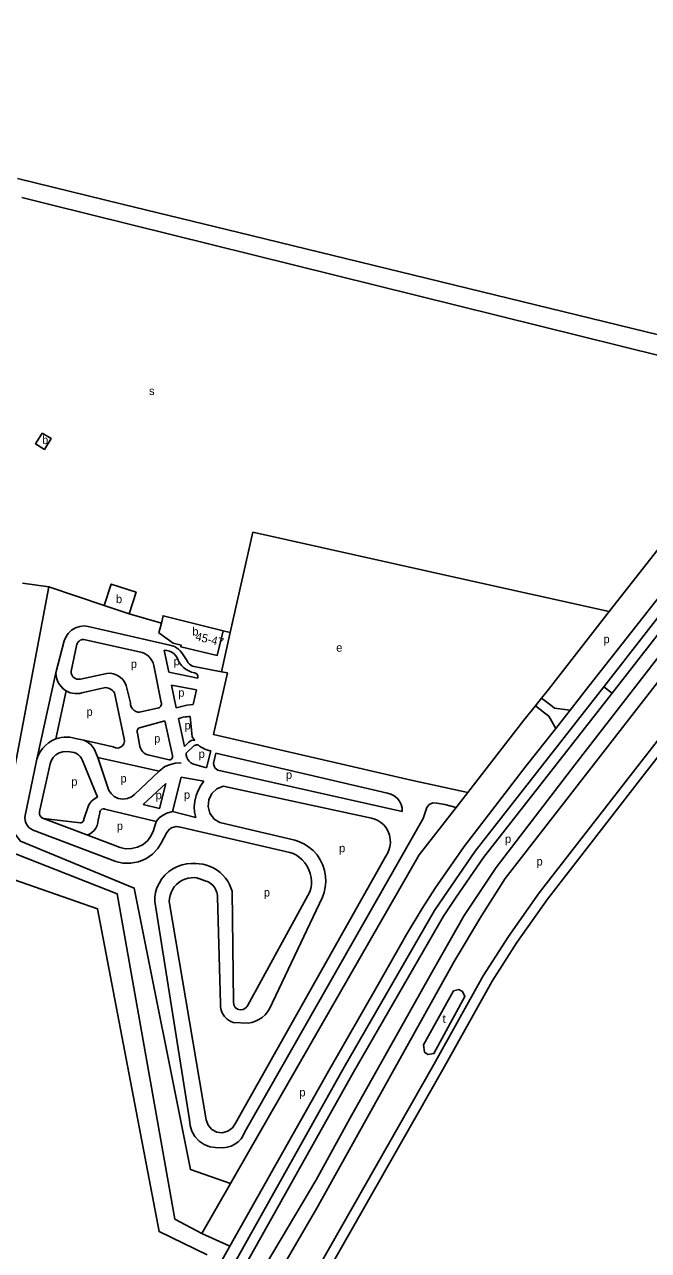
# Model space of a CAD drawing. Extents: x 153608 to 155459, y 385052 to 386919.
# Drawn here: x 154062 to 154363, y 385663 to 386253 of the extents above; entities that cross this region are included whole.
import ezdxf

# ---------------------------------------------------------------- set-up
doc = ezdxf.new("R2010")
doc.units = 0
for name, color, linetype in [('BLT_Basislijn', 7, 'Continuous'), ('BLT_Bebouwing', 7, 'Continuous'), ('BLT_Centroide', 7, 'Continuous'), ('BLT_Gemeentegrens', 7, 'Continuous'), ('BLT_Huisnummer_reeks', 7, 'Continuous'), ('BLT_Vlakafsluiter', 7, 'Continuous')]:
    doc.layers.add(name, color=color, linetype=linetype)

msp = doc.modelspace()

# ---------------------------------------------------------------- linework, layer by layer
at = {"layer": 'BLT_Basislijn'}
for p, q in [((154343.74, 385970.46), (154428.43, 386078.64)), ((154380, 385993.06), (154333.96, 385934.36)), ((154112.53, 385969.36), (154128.11, 385964.85)), ((154314.48, 385932.86), (154343.74, 385970.46)), ((154132.15, 385954.21), (154092.92, 385963.26)), ((154081.38, 385956.23), (154077.28, 385940.91)), ((154090.78, 385957), (154118.86, 385950.68)), ((154161.31, 385960.37), (154157.84, 385961.14)), ((154084.67, 385941.66), (154087.47, 385954.68)), ((154129.5, 385951.72), (154131.67, 385941.23)), ((154124.43, 385944.44), (154127.98, 385926.63)), ((154138.63, 385949.56), (154140.28, 385947.07)), ((154068.09, 385899.23), (154077.28, 385940.91)), ((154101.77, 385940.59), (154089.17, 385937.87)), ((154131.67, 385941.23), (154145.65, 385938.27)), ((154157.02, 385941.36), (154144.65, 385943.72)), ((154159.98, 385940.8), (154157.02, 385941.36)), ((154101.16, 385933.72), (154089.86, 385931.2)), ((154113.19, 385926.34), (154111.16, 385934.8)), ((154132.98, 385934.91), (154135.26, 385923.92)), ((154132.98, 385934.91), (154144.99, 385932.74)), ((154144.99, 385932.74), (154143.36, 385925.62)), ((154311.21, 385928.66), (154314.48, 385932.86)), ((154082.19, 385932.19), (154077.25, 385908.99)), ((154105.51, 385931.23), (154110.23, 385909.11)), ((154308.22, 385924.92), (154311.21, 385928.66)), ((154126.84, 385924.04), (154117.64, 385921.89)), ((154302.67, 385918), (154308.22, 385924.92)), ((154129.85, 385917.79), (154117.5, 385914.35)), ((154129.85, 385917.79), (154133.45, 385900.97)), ((154136.31, 385918.84), (154139.19, 385905.37)), ((154275.66, 385883.18), (154302.67, 385918)), ((154090.78, 385908.37), (154086.74, 385909.29)), ((154116.64, 385911.76), (154117.62, 385906.31)), ((154104.84, 385905.16), (154090.78, 385908.37)), ((154143.96, 385905.81), (154140.03, 385902.16)), ((154151.93, 385903.35), (154149.84, 385895.11)), ((154068.09, 385899.23), (154062.52, 385872.18)), ((154090.12, 385898.63), (154097.43, 385880.95)), ((154097.51, 385900.12), (154102.83, 385884.24)), ((154131.9, 385899.01), (154121.54, 385901.4)), ((154154.36, 385902.2), (154153.55, 385898.62)), ((154154.36, 385902.2), (154237.02, 385882.83)), ((154069.55, 385874.64), (154074.49, 385896.95)), ((154144.14, 385896.64), (154149.84, 385895.11)), ((154244.1, 385874), (154155.25, 385893.99)), ((154137.58, 385890.66), (154133.49, 385874.04)), ((154137.58, 385890.66), (154148.62, 385888.63)), ((154229.35, 385870.87), (154157.87, 385886.23)), ((154248.4, 385889.17), (154275.66, 385883.18)), ((154275.66, 385883.18), (154270.01, 385875.97)), ((154093.02, 385876.99), (154090.81, 385870.4)), ((154133.49, 385874.04), (154144.62, 385871.16)), ((154252.22, 385853.21), (154270.01, 385875.97)), ((154071.38, 385870.62), (154088.94, 385868.53)), ((154071.38, 385870.62), (154092.22, 385862.74)), ((154098.47, 385873.48), (154097.71, 385869.89)), ((154192.41, 385860.2), (154156.31, 385868.68)), ((154168.29, 385719.69), (154254.17, 385870.67)), ((154106.12, 385850.02), (154066.38, 385865.11)), ((154108.29, 385856.66), (154092.22, 385862.74)), ((154130.73, 385863.86), (154128.24, 385859.14)), ((154189.99, 385854.36), (154137.28, 385866.51)), ((154236.21, 385852.58), (154163.78, 385723.83)), ((154155.15, 385832.84), (154156.52, 385781.55)), ((154162.17, 385835.65), (154162.79, 385782.29)), ((154199.64, 385835.32), (154169.57, 385780.49)), ((154205.67, 385832.83), (154180.22, 385779.05)), ((154124.9, 385830.74), (154141.68, 385725.43)), ((154131.9, 385830.75), (154149.74, 385725.43)), ((154162.65, 385772.46), (154169.84, 385772.04)), ((154263.62, 385749.77), (154197.88, 385634.26)), ((154154.12, 385712.15), (154158, 385712.09)), ((154147.56, 385670.72), (154161.11, 385664.72)), ((154161.11, 385664.72), (154156.56, 385656.65))]:
    msp.add_line(p, q, dxfattribs=at)
for points in [[(154745.51, 386395.94), (154651.35, 386298.5), (154593.06, 386237.32), (154585.71, 386228.52), (154550.39, 386183.09), (154493.67, 386110.22), (154463.08, 386071.36), (154405.83, 385998.1), (154327.19, 385896.61), (154289.38, 385847.11), (154273.88, 385824), (154259.18, 385798.01), (154218.87, 385726.19), (154202.46, 385696.25), (154159, 385622.99), (154144.16, 385603.56), (154139.31, 385598.7), (154138.16, 385595.98)], [(154754.37, 386395.71), (154615.6, 386250.29), (154597.76, 386230.66), (154569.71, 386196.31), (154538.03, 386154.95), (154452.53, 386046.43), (154357.94, 385924.71), (154293.71, 385841.85), (154282.27, 385823.81), (154269.07, 385801.81), (154202.93, 385683.02), (154166.56, 385620.26), (154155.85, 385605), (154148.23, 385596.21), (154143.53, 385591.51), (154141.05, 385591.43)], [(154640.74, 386253.44), (154625.05, 386236.37), (154609.33, 386219.18), (154597.17, 386204.41), (154577.98, 386180.02), (154525.27, 386111.88), (154477.44, 386050.65), (154421.65, 385978.46), (154354.9, 385892.7), (154310.03, 385834.83), (154295.19, 385813.79), (154283.1, 385794.92), (154259.28, 385752.24)], [(154341.17, 385934.15), (154392.73, 386000.27), (154500.64, 386139.76), (154565.87, 386224.01), (154579.08, 386240.21), (154593.88, 386257.02)], [(154597.57, 386253.65), (154582.89, 386236.98), (154569.79, 386220.89), (154504.59, 386136.7), (154396.67, 385997.21), (154345.11, 385931.07)], [(154060.93, 386169.83), (154073.68, 386166.67), (154428.43, 386078.64)], [(154161.31, 385960.37), (154172.2, 386008.69)], [(154172.2, 386008.69), (154272.86, 385986.18)], [(154272.86, 385986.18), (154343.74, 385970.46)], [(154073.89, 385982.25), (154053.98, 385876.82), (154054.7, 385867.21), (154060.23, 385859.76), (154115.02, 385837.17), (154142.08, 385701.54), (154161.36, 385694.78)], [(154061.3, 385983.98), (154073.89, 385982.25)], [(154073.89, 385982.25), (154100.55, 385973.24)], [(154092.92, 385963.26), (154090.93, 385963.45), (154088.83, 385963.21), (154086.76, 385962.5), (154084.87, 385961.35), (154083.3, 385959.84), (154082.13, 385958.08), (154081.38, 385956.23)], [(154090.78, 385957), (154090.19, 385956.95), (154089.6, 385956.8), (154089.02, 385956.53), (154088.51, 385956.17), (154088.07, 385955.72), (154087.72, 385955.21), (154087.47, 385954.68)], [(154157.02, 385941.36), (154161.31, 385960.37)], [(154118.86, 385950.68), (154119.99, 385950.21), (154121.06, 385949.57), (154122.04, 385948.76), (154122.89, 385947.81), (154123.58, 385946.74), (154124.09, 385945.61), (154124.43, 385944.44)], [(154129.5, 385951.72), (154130.71, 385951.66), (154131.94, 385951.36), (154133.12, 385950.83), (154134.19, 385950.07), (154135.08, 385949.13), (154135.77, 385948.07), (154136.23, 385946.95)], [(154138.63, 385949.56), (154137.99, 385950.52), (154137.23, 385951.41), (154136.36, 385952.21), (154135.39, 385952.91), (154134.35, 385953.48), (154133.27, 385953.91), (154132.15, 385954.21)], [(154136.23, 385946.95), (154136.89, 385945.68), (154137.74, 385944.47), (154138.78, 385943.39), (154139.97, 385942.47), (154141.28, 385941.75), (154142.66, 385941.24), (154144.07, 385940.94)], [(154144.65, 385943.72), (154143.86, 385943.85), (154143.07, 385944.11), (154142.32, 385944.51), (154141.64, 385945.03), (154141.07, 385945.65), (154140.61, 385946.34), (154140.28, 385947.07)], [(154082.19, 385932.19), (154081.01, 385933.04), (154079.94, 385934.08), (154079.02, 385935.27), (154078.27, 385936.6), (154077.73, 385938.01), (154077.4, 385939.47), (154077.28, 385940.91)], [(154084.67, 385941.66), (154084.7, 385940.77), (154084.98, 385939.83), (154085.55, 385938.96), (154086.36, 385938.28), (154087.32, 385937.87), (154088.29, 385937.75), (154089.17, 385937.87)], [(154101.77, 385940.59), (154103.39, 385940.64), (154105.07, 385940.37), (154106.71, 385939.76), (154108.21, 385938.84), (154109.48, 385937.65), (154110.48, 385936.27), (154111.16, 385934.8)], [(154144.07, 385940.94), (154144.5, 385940.78), (154144.92, 385940.52), (154145.27, 385940.15), (154145.54, 385939.71), (154145.69, 385939.22), (154145.72, 385938.73), (154145.65, 385938.27)], [(154248.4, 385889.17), (154153.23, 385911.1), (154159.98, 385940.8)], [(154101.16, 385933.72), (154101.89, 385933.67), (154102.62, 385933.5), (154103.33, 385933.23), (154103.99, 385932.85), (154104.59, 385932.37), (154105.1, 385931.83), (154105.51, 385931.23)], [(154133.5, 385604.62), (154133.38, 385605.56), (154133.36, 385606.42), (154133.41, 385607.28), (154133.55, 385608.13), (154133.76, 385608.97), (154134.05, 385609.78), (154134.42, 385610.56), (154134.86, 385611.3), (154135.36, 385612.01), (154138.54, 385616.04), (154142.15, 385620.5), (154164.86, 385659.31), (154216.2, 385750.91), (154259.7, 385826.29), (154265.85, 385835.59), (154279.22, 385854.9), (154341.17, 385934.15)], [(154333.96, 385934.36), (154324.93, 385922.88)], [(154089.86, 385931.2), (154088.77, 385930.96), (154087.64, 385930.84), (154086.5, 385930.86), (154085.36, 385931), (154084.25, 385931.28), (154083.18, 385931.68), (154082.19, 385932.19)], [(154345.11, 385931.07), (154283.24, 385851.94), (154269.99, 385832.79), (154263.95, 385823.66), (154220.55, 385748.44), (154169.2, 385656.83), (154146.27, 385617.65), (154142.45, 385612.92), (154142.19, 385612.59)], [(154315.61, 385925.27), (154311.21, 385928.66)], [(154117.64, 385921.89), (154116.72, 385921.98), (154115.77, 385922.3), (154114.89, 385922.84), (154114.15, 385923.58), (154113.6, 385924.47), (154113.29, 385925.41), (154113.19, 385926.34)], [(154127.98, 385926.63), (154128.09, 385926.22), (154128.11, 385925.77), (154128.03, 385925.32), (154127.84, 385924.88), (154127.55, 385924.52), (154127.21, 385924.23), (154126.84, 385924.04)], [(154143.36, 385925.62), (154140.39, 385925.34), (154135.26, 385923.92)], [(154312.69, 385921.51), (154308.22, 385924.92)], [(154318.01, 385914.09), (154314.61, 385920.05), (154312.69, 385921.51)], [(154324.93, 385922.88), (154317.48, 385923.82), (154315.61, 385925.27)], [(154324.93, 385922.88), (154318.01, 385914.09)], [(154141.94, 385919.81), (154141.13, 385919.79), (154140.31, 385919.73), (154139.49, 385919.63), (154138.68, 385919.49), (154137.88, 385919.31), (154137.09, 385919.09), (154136.31, 385918.84)], [(154141.94, 385919.81), (154142.62, 385913.2), (154142.94, 385910.04), (154144.1, 385908.41), (154142.42, 385908.27), (154141.4, 385907.46), (154139.19, 385905.37)], [(154381.51, 385918.75), (154358.84, 385889.63), (154314.05, 385831.86), (154299.34, 385811), (154287.39, 385792.35), (154263.62, 385749.77)], [(154077.25, 385908.99), (154075.48, 385908.2), (154073.79, 385907.17), (154072.24, 385905.9), (154070.86, 385904.43), (154069.69, 385902.8), (154068.77, 385901.05), (154068.09, 385899.23)], [(154086.74, 385909.29), (154085.41, 385909.6), (154084.05, 385909.8), (154082.67, 385909.88), (154081.28, 385909.83), (154079.9, 385909.67), (154078.56, 385909.39), (154077.25, 385908.99)], [(154110.23, 385909.11), (154110.34, 385907.91), (154110.02, 385906.7), (154109.33, 385905.68), (154108.38, 385904.98), (154107.19, 385904.63), (154105.94, 385904.69), (154104.84, 385905.16)], [(154117.5, 385914.35), (154117.16, 385914.13), (154116.86, 385913.82), (154116.62, 385913.44), (154116.48, 385913.01), (154116.44, 385912.57), (154116.5, 385912.14), (154116.64, 385911.76)], [(154318.01, 385914.09), (154303.83, 385896.06), (154273.91, 385857.24), (154259.91, 385837.08)], [(154097.51, 385900.12), (154095.74, 385904.28), (154094.26, 385906.2), (154092.32, 385907.66), (154090.78, 385908.37)], [(154117.62, 385906.31), (154117.73, 385905.4), (154118.02, 385904.49), (154118.48, 385903.62), (154119.1, 385902.84), (154119.85, 385902.2), (154120.67, 385901.72), (154121.54, 385901.4)], [(154145.77, 385906.21), (154145.51, 385906.2), (154145.24, 385906.17), (154144.98, 385906.13), (154144.72, 385906.08), (154144.46, 385906), (154144.21, 385905.92), (154143.96, 385905.81)], [(154151.93, 385903.35), (154150.97, 385903.52), (154150.02, 385903.78), (154149.09, 385904.12), (154148.19, 385904.54), (154147.34, 385905.03), (154146.53, 385905.59), (154145.77, 385906.21)], [(154084, 385902.8), (154082.36, 385903.01), (154080.6, 385902.85), (154078.85, 385902.28), (154077.27, 385901.31), (154075.97, 385900.01), (154075.04, 385898.51), (154074.49, 385896.95)], [(154084, 385902.8), (154085.07, 385902.71), (154086.16, 385902.43), (154087.21, 385901.96), (154088.16, 385901.31), (154088.99, 385900.51), (154089.64, 385899.6), (154090.12, 385898.63)], [(154097.51, 385900.12), (154126.97, 385893.55)], [(154126.97, 385893.55), (154129.73, 385895.66), (154132.01, 385896.59), (154134.8, 385897.27), (154137.65, 385897.55)], [(154133.45, 385900.97), (154133.53, 385900.6), (154133.51, 385900.18), (154133.35, 385899.75), (154133.07, 385899.38), (154132.69, 385899.13), (154132.28, 385899.01), (154131.9, 385899.01)], [(154140.03, 385902.16), (154140.12, 385901.15), (154140.4, 385900.14), (154140.87, 385899.17), (154141.51, 385898.3), (154142.31, 385897.57), (154143.2, 385897.01), (154144.14, 385896.64)], [(154153.55, 385898.62), (154153.33, 385897.93), (154153.26, 385897.15), (154153.36, 385896.36), (154153.64, 385895.59), (154154.08, 385894.92), (154154.63, 385894.38), (154155.25, 385893.99)], [(154126.97, 385893.55), (154115.14, 385882.27)], [(154148.62, 385888.63), (154147.07, 385886.55), (154145.78, 385884.22), (154144.81, 385881.7), (154144.2, 385879.06), (154143.97, 385876.37), (154144.12, 385873.71), (154144.62, 385871.16)], [(154157.87, 385886.23), (154154.85, 385885), (154152.34, 385882.66), (154150.88, 385879.61), (154150.6, 385876.43), (154151.5, 385873.18), (154153.55, 385870.43), (154156.31, 385868.68)], [(154097.43, 385880.95), (154096.65, 385880.61), (154095.9, 385880.18), (154095.19, 385879.67), (154094.53, 385879.08), (154093.95, 385878.43), (154093.45, 385877.73), (154093.02, 385876.99)], [(154102.83, 385884.24), (154103.86, 385882.67), (154105.4, 385881.29), (154107.38, 385880.33), (154109.6, 385879.98), (154111.78, 385880.27), (154113.67, 385881.1), (154115.14, 385882.27)], [(154237.02, 385882.83), (154238.62, 385882.38), (154240.19, 385881.57), (154241.59, 385880.42), (154242.74, 385878.99), (154243.56, 385877.37), (154244.01, 385875.67), (154244.1, 385874)], [(154069.55, 385874.64), (154069.39, 385874.01), (154069.36, 385873.31), (154069.5, 385872.6), (154069.81, 385871.93), (154070.25, 385871.35), (154070.8, 385870.91), (154071.38, 385870.62)], [(154100.96, 385875.2), (154100.52, 385875.31), (154100.01, 385875.3), (154099.5, 385875.14), (154099.05, 385874.82), (154098.71, 385874.4), (154098.52, 385873.94), (154098.47, 385873.48)], [(154100.96, 385875.2), (154125.66, 385869.24)], [(154125.66, 385869.24), (154126.97, 385870.93), (154128.71, 385872.18), (154130.81, 385873.27), (154133.49, 385874.04)], [(154254.17, 385870.67), (154255.93, 385875.97), (154257.13, 385877.44), (154258.85, 385878.24), (154260.7, 385878.15), (154264.6, 385877.35), (154270.01, 385875.97)], [(154062.52, 385872.18), (154062.4, 385871), (154062.52, 385869.76), (154062.9, 385868.53), (154063.52, 385867.4), (154064.35, 385866.42), (154065.33, 385865.65), (154066.38, 385865.11)], [(154090.81, 385870.4), (154090.77, 385870.01), (154090.64, 385869.62), (154090.41, 385869.25), (154090.1, 385868.93), (154089.73, 385868.71), (154089.33, 385868.57), (154088.94, 385868.53)], [(154097.71, 385869.89), (154097.59, 385868.57), (154097.22, 385867.24), (154096.59, 385865.97), (154095.72, 385864.84), (154094.65, 385863.9), (154093.46, 385863.19), (154092.22, 385862.74)], [(154125.66, 385869.24), (154124.3, 385864.9)], [(154229.35, 385870.87), (154230.84, 385870.42), (154232.34, 385869.73), (154233.8, 385868.78), (154235.15, 385867.57), (154236.34, 385866.11), (154237.3, 385864.45), (154237.98, 385862.64), (154238.35, 385860.76), (154238.41, 385858.89), (154238.18, 385857.08), (154237.7, 385855.41), (154237.03, 385853.9), (154236.21, 385852.58)], [(154124.3, 385864.9), (154123.22, 385862.45), (154121.54, 385860.16), (154119.29, 385858.23), (154116.62, 385856.86), (154113.74, 385856.15), (154110.9, 385856.12), (154108.29, 385856.66)], [(154137.28, 385866.51), (154136.26, 385866.73), (154135.17, 385866.75), (154134.06, 385866.55), (154133.01, 385866.12), (154132.07, 385865.5), (154131.3, 385864.73), (154130.73, 385863.86)], [(154038.94, 385861.11), (154106.86, 385834.44), (154134.59, 385677.64)], [(154128.24, 385859.14), (154126.36, 385856.16), (154123.8, 385853.46), (154120.64, 385851.28), (154117.05, 385849.8), (154113.27, 385849.12), (154109.55, 385849.22), (154106.12, 385850.02)], [(154192.41, 385860.2), (154194.68, 385859.45), (154196.96, 385858.37), (154199.16, 385856.95), (154201.22, 385855.2), (154203.07, 385853.13), (154204.64, 385850.8), (154205.87, 385848.25), (154206.73, 385845.58), (154207.21, 385842.85), (154207.3, 385840.14), (154207.05, 385837.54), (154206.49, 385835.08), (154205.67, 385832.83)], [(154161.36, 385694.78), (154170.2, 385710.19), (154252.22, 385853.21)], [(154189.99, 385854.36), (154191.56, 385853.75), (154193.1, 385852.94), (154194.59, 385851.92), (154195.98, 385850.69), (154197.23, 385849.27), (154198.3, 385847.68), (154199.17, 385845.97), (154199.81, 385844.17), (154200.22, 385842.32), (154200.39, 385840.47), (154200.33, 385838.67), (154200.08, 385836.94), (154199.64, 385835.32)], [(154144.67, 385848.97), (154142.55, 385849.05), (154140.34, 385848.87), (154138.08, 385848.4), (154135.84, 385847.62), (154133.66, 385846.51), (154131.64, 385845.1), (154129.81, 385843.42), (154128.24, 385841.51), (154126.97, 385839.44), (154126, 385837.26), (154125.35, 385835.05), (154124.99, 385832.86), (154124.9, 385830.74)], [(154144.67, 385848.97), (154146.38, 385848.89), (154148.13, 385848.63), (154149.88, 385848.2), (154151.61, 385847.59), (154153.3, 385846.79), (154154.9, 385845.81), (154156.4, 385844.67), (154157.77, 385843.38), (154158.99, 385841.97), (154160.04, 385840.47), (154160.93, 385838.89), (154161.63, 385837.28), (154162.17, 385835.65)], [(154036.15, 385621), (153965.08, 385743.39), (153948.41, 385766.59), (153953.77, 385773.54), (153976.51, 385795.97), (154002.85, 385807.54), (154028.24, 385814.09), (154041.04, 385819.77), (154047.68, 385825.72), (154056.95, 385841.28), (154097.32, 385827.18), (154127.02, 385671.7), (154150.21, 385660.41)], [(154145.24, 385842.05), (154143.87, 385842.18), (154142.42, 385842.14), (154140.93, 385841.91), (154139.44, 385841.47), (154137.99, 385840.81), (154136.63, 385839.95), (154135.39, 385838.9), (154134.31, 385837.7), (154133.43, 385836.37), (154132.75, 385834.98), (154132.27, 385833.55), (154132, 385832.13), (154131.9, 385830.75)], [(154149.56, 385840.52), (154149.22, 385840.64), (154148.89, 385840.76), (154148.56, 385840.88), (154148.23, 385840.99), (154147.9, 385841.11), (154147.56, 385841.23), (154147.23, 385841.35), (154146.9, 385841.46), (154146.57, 385841.58), (154146.23, 385841.7), (154145.9, 385841.81), (154145.57, 385841.93), (154145.24, 385842.05)], [(154149.56, 385840.52), (154150.25, 385840.27), (154150.93, 385839.93), (154151.6, 385839.53), (154152.23, 385839.06), (154152.82, 385838.52), (154153.36, 385837.92), (154153.83, 385837.26), (154154.24, 385836.57), (154154.57, 385835.84), (154154.83, 385835.09), (154155.01, 385834.34), (154155.12, 385833.58), (154155.15, 385832.84)], [(154259.91, 385837.08), (154253.64, 385827.35), (154246.15, 385814.85), (154232.45, 385790.72), (154208.56, 385749), (154161.11, 385664.72)], [(154156.52, 385781.55), (154156.54, 385779.94), (154156.87, 385778.29), (154157.53, 385776.68), (154158.51, 385775.22), (154159.75, 385774), (154161.16, 385773.08), (154162.65, 385772.46)], [(154162.79, 385782.29), (154162.97, 385780.94), (154163.7, 385779.7), (154164.82, 385778.86), (154166.1, 385778.52), (154167.5, 385778.69), (154168.74, 385779.41), (154169.57, 385780.49)], [(154180.22, 385779.05), (154179.23, 385777.54), (154178.02, 385776.14), (154176.61, 385774.89), (154175.05, 385773.83), (154173.37, 385773), (154171.62, 385772.4), (154169.84, 385772.04)], [(154259.28, 385752.24), (154181.22, 385615.1), (154171.8, 385599.9), (154164.99, 385590.65), (154158.15, 385583.98), (154150.4, 385576.64)], [(154141.68, 385725.43), (154141.92, 385722.74), (154142.76, 385720.01), (154144.25, 385717.43), (154146.31, 385715.23), (154148.78, 385713.58), (154151.46, 385712.56), (154154.12, 385712.15)], [(154149.74, 385725.43), (154150.63, 385722.94), (154152.46, 385720.85), (154154.89, 385719.59), (154157.45, 385719.3), (154160.1, 385719.97), (154162.35, 385721.61), (154163.78, 385723.83)], [(154168.29, 385719.69), (154167.55, 385717.98), (154166.49, 385716.35), (154165.12, 385714.9), (154163.51, 385713.71), (154161.72, 385712.83), (154159.85, 385712.29), (154158, 385712.09)], [(154147.56, 385670.72), (154161.36, 385694.78)], [(154134.59, 385677.64), (154147.56, 385670.72)]]:
    msp.add_lwpolyline(points, dxfattribs=at)
for points in [[(154130.21, 385887.62), (154127.23, 385875.55), (154119.38, 385877.49)], [(154268.69, 385787.71), (154271.33, 385788.23), (154273.17, 385787.27), (154274.28, 385784.99), (154259.35, 385757.42), (154256.48, 385756.98), (154254.86, 385758.15), (154254.35, 385761.68)]]:
    msp.add_lwpolyline(points, close=True, dxfattribs=at)
at = {"layer": 'BLT_Bebouwing'}
msp.add_line((154112.53, 385969.36), (154100.55, 385973.24), dxfattribs=at)
msp.add_lwpolyline([(154070.78, 386056.4), (154075.09, 386053.7), (154071.82, 386048.48), (154067.51, 386051.18)], close=True, dxfattribs=at)
for points in [[(154100.55, 385973.24), (154103.95, 385983.6), (154115.92, 385979.67), (154112.53, 385969.36)], [(154128.11, 385964.85), (154128.94, 385968.34), (154157.84, 385961.14)], [(154157.84, 385961.14), (154155.03, 385949.27), (154137.4, 385953.43), (154137.58, 385954.2), (154133.78, 385955.1), (154126.96, 385960.07), (154128.11, 385964.85)]]:
    msp.add_lwpolyline(points, dxfattribs=at)
at = {"layer": 'BLT_Gemeentegrens'}
msp.add_line((154165.43, 386152.97), (154281.95, 386124.59), dxfattribs=at)
for points in [[(154058.77, 386178.94), (154109.18, 386166.68), (154165.43, 386152.97)], [(154281.95, 386124.59), (154407.66, 386093.98), (154440.56, 386085.97)]]:
    msp.add_lwpolyline(points, dxfattribs=at)
at = {"layer": 'BLT_Vlakafsluiter'}
msp.add_line((154341.17, 385934.15), (154345.11, 385931.07), dxfattribs=at)

# ---------------------------------------------------------------- texts
at = {"layer": 'BLT_Centroide'}
for s, p in [('s', (154122.13, 386074.68)), ('b', (154070.68, 386051.06)), ('b', (154106.24, 385974.44)), ('b', (154143, 385958.81)), ('p', (154340.99, 385955.14)), ('e', (154212.3, 385951.03)), ('p', (154113.39, 385943.2)), ('p', (154133.99, 385944.52)), ('p', (154136.22, 385929.36)), ('p', (154092.05, 385920.17)), ('p', (154139.25, 385913.58)), ('p', (154124.63, 385907.25)), ('p', (154146.03, 385899.85)), ('p', (154188.08, 385889.8)), ('p', (154084.74, 385886.46)), ('p', (154108.4, 385888.02)), ('p', (154125.34, 385879.97)), ('p', (154138.96, 385880.17)), ('p', (154106.65, 385865.12)), ('p', (154293.57, 385858.9)), ('p', (154213.67, 385854.44)), ('p', (154308.75, 385848.05)), ('p', (154177.44, 385833.09)), ('t', (154263.54, 385772.24)), ('p', (154194.53, 385736.78))]:
    msp.add_text(s, height=4, dxfattribs=at).set_placement(p)
at = {"layer": 'BLT_Huisnummer_reeks'}
msp.add_text('45-47', height=4, rotation=346.71838, dxfattribs=at).set_placement((154144.26, 385956.61))

doc.saveas('drawing.dxf')
